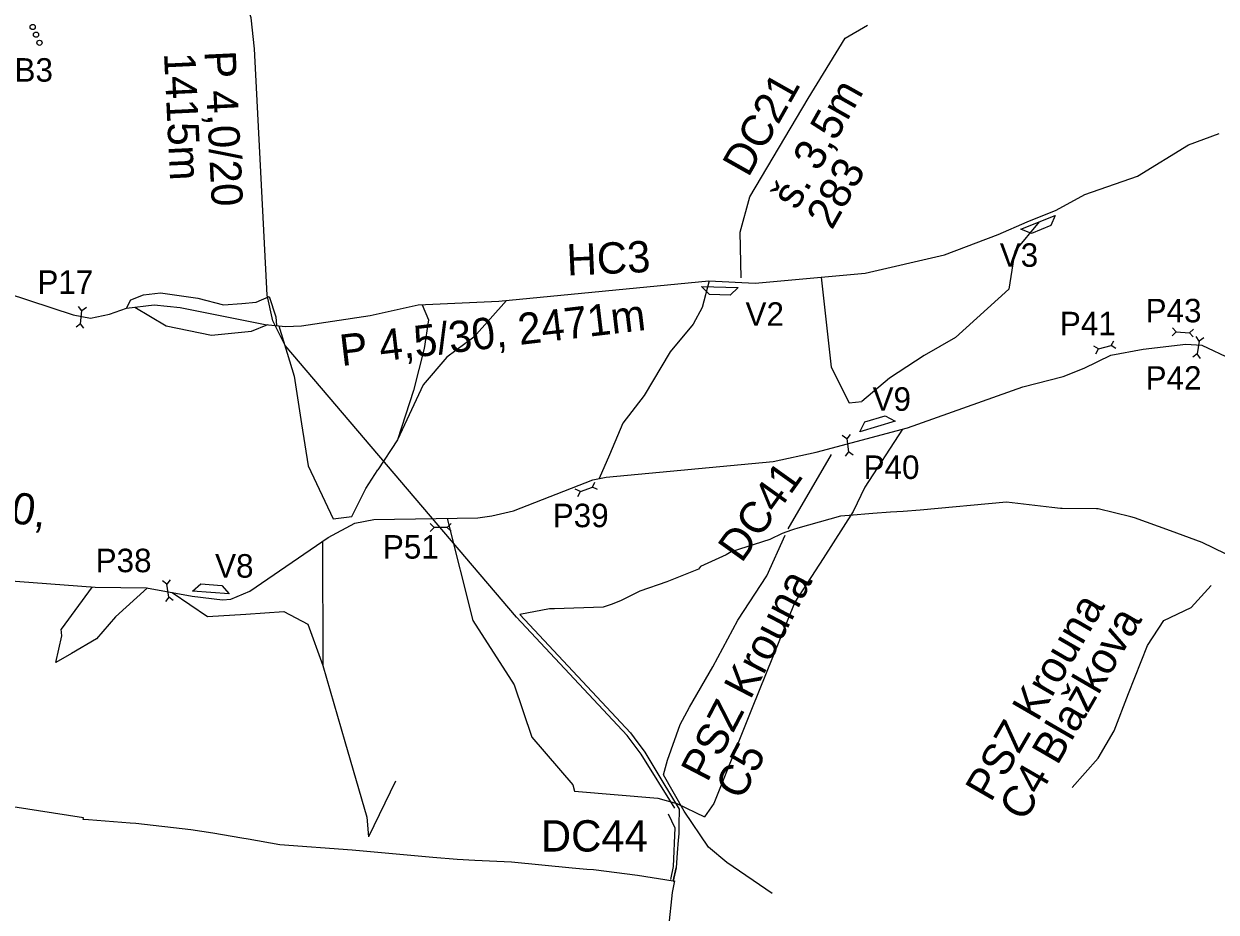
# Model space of a CAD drawing. Extents: x -638669 to -632369, y -1091026 to -1088056.
# Drawn here: x -634652 to -633510, y -1090018 to -1089167 of the extents above; entities that cross this region are included whole.
import ezdxf

# ---------------------------------------------------------------- set-up
doc = ezdxf.new("R2010")
doc.units = 0
for name, color, linetype in [('01_OBVOD PÚ', 7, 'Continuous'), ('01_SPRÁV_HRANICE_STAV', 7, 'Continuous'), ('03_PC_MIMO_OBVOD', 7, 'Continuous'), ('03_PC_NÁVRH', 7, 'Continuous'), ('03_PC_OBJEKTY_NÁVRH', 7, 'Continuous'), ('03_PC_OBJEKTY_STAV', 7, 'Continuous'), ('03_PC_POPIS_NÁVRH', 7, 'Continuous'), ('03_PC_POPIS_STAV', 7, 'Continuous'), ('03_PC_STAV', 7, 'Continuous'), ('05_VHO_ROZVODÍ', 7, 'Continuous')]:
    doc.layers.add(name, color=color, linetype=linetype)

msp = doc.modelspace()

# ---------------------------------------------------------------- linework, layer by layer
at = {"layer": '01_OBVOD PÚ'}
msp.add_lwpolyline([(-633500.8, -1089674.8), (-633523.1, -1089663.9), (-633553.7, -1089652.9), (-633588.2, -1089640.4), (-633591.6, -1089639.5), (-633622.7, -1089631.8), (-633624.3, -1089631.7), (-633657.2, -1089631.5), (-633658.8, -1089631.5), (-633667.1, -1089630.5), (-633710.5, -1089625.2), (-633793.4, -1089632.9), (-633809.7, -1089634.1), (-633821.8, -1089634.9), (-633838.7, -1089636.2), (-633861.4, -1089638), (-633869.7, -1089638.6), (-633910.6, -1089650.3), (-633914.5, -1089651.4), (-633916.7, -1089652), (-633925.5, -1089655.4), (-633937.3, -1089661.1), (-633974.4, -1089672.9), (-633979.1, -1089675.9), (-634003.7, -1089687), (-634005.7, -1089689.5), (-634036, -1089701.5), (-634061.8, -1089710.4), (-634079.6, -1089719.6), (-634088.4, -1089722.9), (-634097, -1089726), (-634143.4, -1089727.5), (-634148.4, -1089727.6), (-634176.7, -1089732.8), (-634158.3, -1089752.6), (-634070.8, -1089846.1), (-634067.1, -1089851), (-634056.9, -1089864.7), (-634040.6, -1089892), (-634024.3, -1089919.4), (-634024.5, -1089934.6), (-634024.6, -1089940.2), (-634024.6, -1089943.1), (-634025.1, -1089948.9), (-634026, -1089961.2), (-634027, -1089975.4), (-634029.9, -1089988.2), (-634064, -1089982.8), (-634106.1, -1089977.5), (-634112.5, -1089977), (-634126.7, -1089975.9), (-634184.8, -1089970.1), (-634219.8, -1089968.4), (-634236.7, -1089967.6), (-634260, -1089965.6), (-634337.4, -1089958.7), (-634406.6, -1089953.5), (-634437, -1089948.2), (-634443, -1089947.2), (-634470.7, -1089942.4), (-634491.8, -1089939.1), (-634544.5, -1089933.2), (-634550, -1089932.8), (-634590, -1089929.6), (-634595, -1089929.3), (-634594.6, -1089927.7), (-634773.4, -1089899.8)], dxfattribs=at)
at = {"layer": '01_SPRÁV_HRANICE_STAV'}
for points in [[(-633500.8, -1089674.8), (-633523.1, -1089663.9), (-633553.7, -1089652.9), (-633588.2, -1089640.4), (-633591.6, -1089639.5), (-633622.7, -1089631.8), (-633624.3, -1089631.7), (-633657.2, -1089631.5), (-633658.8, -1089631.5), (-633667.1, -1089630.5), (-633710.5, -1089625.2), (-633793.4, -1089632.9), (-633809.7, -1089634.1), (-633821.8, -1089634.9), (-633838.7, -1089636.2), (-633861.4, -1089638), (-633869.7, -1089638.6), (-633910.6, -1089650.3), (-633914.5, -1089651.4), (-633916.7, -1089652), (-633925.5, -1089655.4), (-633937.3, -1089661.1), (-633974.4, -1089672.9), (-633979.1, -1089675.9), (-634003.7, -1089687), (-634005.7, -1089689.5), (-634036, -1089701.5), (-634061.8, -1089710.4), (-634079.6, -1089719.6), (-634088.4, -1089722.9), (-634097, -1089726), (-634143.4, -1089727.5), (-634148.4, -1089727.6), (-634176.7, -1089732.8), (-634158.3, -1089752.6), (-634070.8, -1089846.1), (-634067.1, -1089851), (-634056.9, -1089864.7), (-634040.6, -1089892), (-634024.3, -1089919.4), (-634024.5, -1089934.6), (-634024.6, -1089940.2), (-634024.6, -1089943.1), (-634025.1, -1089948.9), (-634026, -1089961.2), (-634027, -1089975.4), (-634029.9, -1089988.2), (-634064, -1089982.8), (-634106.1, -1089977.5), (-634112.5, -1089977), (-634126.7, -1089975.9), (-634184.8, -1089970.1), (-634219.8, -1089968.4), (-634236.7, -1089967.6), (-634260, -1089965.6), (-634337.4, -1089958.7), (-634406.6, -1089953.5), (-634437, -1089948.2), (-634443, -1089947.2), (-634470.7, -1089942.4), (-634491.8, -1089939.1), (-634544.5, -1089933.2), (-634550, -1089932.8), (-634590, -1089929.6), (-634595, -1089929.3), (-634594.6, -1089927.7), (-634773.4, -1089899.8)], [(-634026, -1089961.2), (-634027, -1089975.4)], [(-634029.9, -1089988.2), (-634027, -1089975.4)], [(-634029.9, -1089988.2), (-634028.5, -1089988.1), (-634031, -1089999.2), (-634038, -1090065.6), (-634038, -1090081.9), (-634038, -1090088.5), (-634035.1, -1090104.4)]]:
    msp.add_lwpolyline(points, dxfattribs=at)
at = {"layer": '03_PC_MIMO_OBVOD'}
for points in [[(-633935, -1090000.2), (-633978.6, -1089970.3), (-633996, -1089955.6), (-634019.3, -1089921.1), (-634039.3, -1089886.3), (-634035.2, -1089872.5), (-634023.3, -1089838.3), (-634014.2, -1089821.6), (-633992, -1089782.9), (-633968.1, -1089738.3), (-633940.2, -1089696), (-633922.5, -1089656.9)], [(-633647.9, -1089898.5), (-633622.8, -1089870.5), (-633607.6, -1089844.4), (-633593.9, -1089808.6), (-633575.6, -1089762.7), (-633559.9, -1089738.5), (-633533.7, -1089726.2), (-633514.5, -1089705.2)]]:
    msp.add_lwpolyline(points, dxfattribs=at)
at = {"layer": '03_PC_NÁVRH'}
for points in [[(-634028.4, -1089918.4), (-634060.5, -1089866.7), (-634073.8, -1089848.9), (-634179.9, -1089735.6), (-634401.5, -1089475.2), (-634413.3, -1089451.8), (-634418.6, -1089427.1), (-634430.9, -1089191.2), (-634434, -1089161.4), (-634444.3, -1089131.2), (-634499.7, -1089030.6), (-634521.3, -1088997.5), (-634529.1, -1088971.5), (-634523.8, -1088947.2), (-634469.9, -1088848.1), (-634448.5, -1088804.7), (-634401.6, -1088701.6)], [(-634667.7, -1089425.1), (-634604.7, -1089446), (-634587.8, -1089449), (-634569.8, -1089445.3), (-634553.4, -1089439.4), (-634527, -1089436.3), (-634502, -1089438.8), (-634420.7, -1089455.1), (-634401.2, -1089457), (-634385.7, -1089456.3), (-634320.2, -1089446.4), (-634274, -1089436.4), (-634196.8, -1089432.9), (-633995.8, -1089413.4), (-633951.2, -1089415.7), (-633846, -1089405.9), (-633769.9, -1089388.3), (-633718.7, -1089368.9), (-633690.8, -1089356.7), (-633663.2, -1089345.6), (-633635.7, -1089330.7), (-633585.1, -1089313), (-633536.2, -1089283.2), (-633506.9, -1089272.1)], [(-634672.6, -1089700.1), (-634583.6, -1089706.6), (-634534.3, -1089707.5), (-634490.7, -1089715.2), (-634461.4, -1089718.9), (-634453.4, -1089718.3), (-634435.2, -1089710.4), (-634360.3, -1089659.3), (-634334.8, -1089645.3), (-634316.6, -1089641.8), (-634216.9, -1089640.3), (-634203.6, -1089638.5), (-634182.8, -1089633.6), (-634106.7, -1089604), (-634093.9, -1089601.5), (-633934, -1089586.3), (-633893, -1089577.4), (-633805.6, -1089554.2), (-633695.1, -1089514.8), (-633656.4, -1089505.1), (-633636.1, -1089497.1), (-633610.6, -1089484.5), (-633579.7, -1089478.9), (-633538.8, -1089474.1), (-633523.7, -1089475.1), (-633466.8, -1089501.9)]]:
    msp.add_lwpolyline(points, dxfattribs=at)
at = {"layer": '03_PC_OBJEKTY_NÁVRH'}
for points in [[(-633664.1, -1089350.7), (-633668.2, -1089360.4), (-633686.8, -1089368), (-633696.8, -1089364)], [(-633967.5, -1089419.7), (-633975.2, -1089427), (-633995.2, -1089426.5), (-634002.7, -1089418.8)], [(-633851.2, -1089557.9), (-633846.2, -1089548.5), (-633827, -1089542.7), (-633817.4, -1089547.7)], [(-634490.3, -1089710.5), (-634482.3, -1089703.6), (-634462.3, -1089705), (-634455.1, -1089713.1)]]:
    msp.add_lwpolyline(points, close=True, dxfattribs=at)
for points in [[(-633521.7, -1089467.9), (-633526, -1089471), (-633529.1, -1089466.7)], [(-633526, -1089471), (-633528, -1089483.4)], [(-633524.9, -1089487.7), (-633528, -1089483.4), (-633532.3, -1089486.5)], [(-633860.5, -1089560.6), (-633863.7, -1089564.8), (-633867.9, -1089561.6)], [(-633863.7, -1089564.8), (-633861.9, -1089577.2)], [(-633857.6, -1089580.3), (-633861.9, -1089577.2), (-633865, -1089581.4)], [(-634262.5, -1089653.3), (-634258.8, -1089649.5), (-634262.5, -1089645.8)], [(-634246.3, -1089649.5), (-634258.8, -1089649.5)], [(-634242.5, -1089653.2), (-634246.3, -1089649.5), (-634242.5, -1089645.7)]]:
    msp.add_lwpolyline(points, dxfattribs=at)
at = {"layer": '03_PC_OBJEKTY_STAV'}
for points in [[(-634591.9, -1089438.8), (-634596.1, -1089442.1), (-634599.4, -1089437.9)], [(-634597.5, -1089454.5), (-634596.1, -1089442.1)], [(-634594.3, -1089458.6), (-634597.5, -1089454.5), (-634601.7, -1089457.8)], [(-633552, -1089465.9), (-633548, -1089462.3), (-633551.5, -1089458.4)], [(-633548, -1089462.3), (-633535.5, -1089463.1)], [(-633532, -1089467.1), (-633535.5, -1089463.1), (-633531.5, -1089459.6)], [(-633625.1, -1089483.2), (-633622.4, -1089478.6), (-633627, -1089476)], [(-633622.4, -1089478.6), (-633610.4, -1089475.4)], [(-633605.8, -1089478.1), (-633610.4, -1089475.4), (-633607.7, -1089470.9)], [(-634121.1, -1089620), (-634118.8, -1089615.2), (-634123.6, -1089612.9)], [(-634118.8, -1089615.2), (-634107, -1089611)], [(-634102.3, -1089613.3), (-634107, -1089611), (-634104.8, -1089606.2)], [(-634511.6, -1089699.7), (-634514.8, -1089703.9), (-634519, -1089700.7)], [(-634513, -1089716.3), (-634514.8, -1089703.9)], [(-634508.7, -1089719.4), (-634513, -1089716.3), (-634516.1, -1089720.5)]]:
    msp.add_lwpolyline(points, dxfattribs=at)
for centre in [(-634643.3, -1089170.2), (-634640.1, -1089177.6), (-634636.8, -1089185.4)]:
    msp.add_circle(centre, 2.5, dxfattribs=at)
at = {"layer": '03_PC_STAV'}
msp.add_line((-633919.8, -1089650.8), (-633878.3, -1089579.6), dxfattribs=at)
for points in [[(-633964.9, -1089410.4), (-633965.7, -1089366.7), (-633956.4, -1089332.9), (-633900.5, -1089238.6), (-633865.2, -1089180.9), (-633843.8, -1089168.6)], [(-634034.6, -1089923.7), (-634028.3, -1089937.1), (-634029.8, -1089974.3), (-634032.5, -1089986.6)]]:
    msp.add_lwpolyline(points, dxfattribs=at)
at = {"layer": '05_VHO_ROZVODÍ'}
for p, q in [((-634586.4, -1089706.4), (-634615.9, -1089747)), ((-634295.8, -1089892.6), (-634321.6, -1089945.9)), ((-634044.6, -1089908.8), (-634026.4, -1089913.8)), ((-634026.4, -1089913.8), (-633999.8, -1089926.8))]:
    msp.add_line(p, q, dxfattribs=at)
for points in [[(-633679.2, -1089356.8), (-633702.7, -1089385), (-633708.3, -1089421.3), (-633759.4, -1089467.5), (-633789.6, -1089484.7), (-633822.7, -1089506.6), (-633849.1, -1089528.9)], [(-633888.2, -1089409.8), (-633878.5, -1089495.9), (-633861.3, -1089530.1), (-633849.1, -1089528.9)], [(-633995.3, -1089413.5), (-634002.1, -1089438.9), (-634010.8, -1089454.9), (-634032.8, -1089481.4), (-634057.7, -1089523.3), (-634078.1, -1089549.5), (-634091, -1089580.1), (-634100.7, -1089602.8)], [(-634553.4, -1089439.4), (-634549.4, -1089431.7), (-634537.3, -1089426.9), (-634521, -1089424.8), (-634485.1, -1089430), (-634460.5, -1089436.4), (-634443, -1089434.9), (-634429.4, -1089433.7), (-634416.7, -1089428.4), (-634410.3, -1089447.9), (-634409.9, -1089456.1)], [(-634189.4, -1089432.2), (-634220.8, -1089467.4), (-634246.7, -1089486.4), (-634269.2, -1089512.9), (-634293.8, -1089565.6)], [(-634545.6, -1089438.5), (-634515.4, -1089456.5), (-634472, -1089465.4), (-634433.8, -1089461.6), (-634418.2, -1089455.3)], [(-634270.2, -1089436.2), (-634264.3, -1089450.8), (-634268.5, -1089478.2), (-634278.6, -1089518.3), (-634293.8, -1089565.6), (-634312.8, -1089594.5)], [(-634407.7, -1089456.3), (-634392.8, -1089504.6), (-634385.8, -1089550.4), (-634379.6, -1089590.4), (-634355.6, -1089641.2), (-634337.6, -1089639), (-634324.2, -1089612.1), (-634312.8, -1089594.5)], [(-633810.3, -1089555.5), (-633846.4, -1089610.8), (-633857.4, -1089634.4), (-633886.3, -1089679.2), (-633913.5, -1089721.2)], [(-634246.5, -1089640.8), (-634221.8, -1089738.7), (-634182.2, -1089800.1), (-634165.3, -1089850.4), (-634125.9, -1089896.1), (-634124.5, -1089902), (-634044.6, -1089908.8)], [(-634365.9, -1089663.1), (-634365.4, -1089781.8), (-634344.3, -1089854.5), (-634323.2, -1089927.1), (-634321.6, -1089945.9)], [(-634533.4, -1089707.5), (-634564, -1089735.2), (-634582.2, -1089756.2), (-634606.2, -1089770.3), (-634621, -1089779), (-634615.3, -1089753.4), (-634615.9, -1089747)], [(-634509.6, -1089711.9), (-634475.9, -1089734.9), (-634439.3, -1089732.5), (-634402.8, -1089730), (-634379.7, -1089742.3), (-634365.4, -1089781.8)], [(-633913.5, -1089721.2), (-633954.8, -1089824), (-633991, -1089913.9), (-633999.8, -1089926.8)]]:
    msp.add_lwpolyline(points, dxfattribs=at)

# ---------------------------------------------------------------- texts
at = {"layer": '03_PC_MIMO_OBVOD'}
for s, rotation, p in [('PSZ Krouna', 62.4607, (-633997.2, -1089894.4)), ('PSZ Krouna', 59.8608, (-633725.6, -1089913.5)), ('C4 Blažkova', 59.8608, (-633693.3, -1089932.2)), ('C5', 62.4607, (-633964.1, -1089911.7))]:
    msp.add_text(s, height=30, rotation=rotation, dxfattribs=at).set_placement(p)
at = {"layer": '03_PC_OBJEKTY_NÁVRH'}
for s, p in [('V3', (-633717.1, -1089399.9)), ('V2', (-633960.6, -1089456.4)), ('P42', (-633577.4, -1089517.6)), ('V9', (-633838.9, -1089537.8)), ('P40', (-633847.5, -1089603.1)), ('P51', (-634307.9, -1089679.4)), ('V8', (-634468.6, -1089697.6))]:
    msp.add_text(s, height=22.5, dxfattribs=at).set_placement(p)
at = {"layer": '03_PC_OBJEKTY_STAV'}
for s, p in [('B3', (-634660.7, -1089222.6)), ('P17', (-634638.8, -1089425.8)), ('P43', (-633577.4, -1089453.1)), ('P41', (-633659.5, -1089465.5)), ('P39', (-634145.2, -1089649.3)), ('P38', (-634583, -1089692.4))]:
    msp.add_text(s, height=22.5, dxfattribs=at).set_placement(p)
at = {"layer": '03_PC_POPIS_NÁVRH'}
for s, rotation, p in [('1415m', 272.7537, (-634517.6, -1089195.3)), ('P 4,0/20', 272.7537, (-634478.9, -1089193.5)), ('HC3', 2.5798, (-634131.3, -1089408.4)), ('P 4,5/30, 2471m', 6.7658, (-634347.4, -1089495)), ('P 4,5/30,', 351.2499, (-634790.9, -1089625.5))]:
    msp.add_text(s, height=30, rotation=rotation, dxfattribs=at).set_placement(p)
at = {"layer": '03_PC_POPIS_STAV'}
for s, rotation, p in [('DC21', 60.54, (-633957.9, -1089315.1)), ('š. 3,5m', 60.54, (-633911.5, -1089346.4)), ('283', 60.54, (-633877.8, -1089365.4)), ('DC41', 54.4559, (-633964.4, -1089684.4))]:
    msp.add_text(s, height=30, rotation=rotation, dxfattribs=at).set_placement(p)
msp.add_text('DC44', height=30, dxfattribs=at).set_placement((-634156.6, -1089959.9))

doc.saveas('drawing.dxf')
